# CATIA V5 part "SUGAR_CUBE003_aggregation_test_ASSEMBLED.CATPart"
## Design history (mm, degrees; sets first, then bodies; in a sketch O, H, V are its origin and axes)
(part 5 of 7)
Body41 "sugar_cube003Be004"
  Line260: type PtDir, RefPoint Point20, Direction edge [XY plane of AxisSystem1 | ZX plane of AxisSystem1], Start 0, End 3657.6 {= Body41.X1}
  Line261: type PtDir, RefPoint Point20, Direction edge [XY plane of AxisSystem1 | ZX plane of AxisSystem1], Start 0, End 6096 {= Body41.X2}
  Line262: type PtDir, RefPoint Point20, Direction edge [YZ plane of AxisSystem1 | XY plane of AxisSystem1], Start 0, End 5791.2 {= Body41.Y1}
  Line263: type PtDir, RefPoint Point20, Direction edge [YZ plane of AxisSystem1 | XY plane of AxisSystem1], Start 0, End 3962.4 {= Body41.Y2}
  Line264: type PtDir, RefPoint Point20, Direction edge [ZX plane of AxisSystem1 | YZ plane of AxisSystem1], Start 0, End 3352.8 {= Body41.Z1}
  Line265: type PtDir, RefPoint Point20, Direction edge [ZX plane of AxisSystem1 | YZ plane of AxisSystem1], Start 0, End 3962.4 {= Body41.Z2}
  Plane518: type Normal, Curve Line260, RefPoint vertex of Line260
  Plane519: type Normal, Curve Line261, RefPoint vertex of Line261
  Plane520: type Normal, Curve Line262, RefPoint vertex of Line262
  Plane521: type Normal, Curve Line263, RefPoint vertex of Line263
  Plane522: type Normal, Curve Line264, RefPoint vertex of Line264
  Plane523: type Normal, Curve Line265, RefPoint vertex of Line265
  Plane524: type 3Points, Element1 Point20, Element2 vertex of Line262, Element3 vertex of Line260
  Intersect781: ToIntersect1 Plane520, ToIntersect2 Plane519
  Intersect782: ToIntersect1 Plane518, ToIntersect2 Plane520
  Intersect783: ToIntersect1 Plane518, ToIntersect2 Plane521
  Intersect784: ToIntersect1 Plane521, ToIntersect2 Plane519
  MultiSel40
  LineCorner40: Elements ({intersect ToIntersect1 Plane524, ToIntersect2 Intersect783}; {intersect ToIntersect1 Plane524, ToIntersect2 Intersect784}; {intersect ToIntersect1 Plane524, ToIntersect2 Intersect781}; {intersect ToIntersect1 Plane524, ToIntersect2 Intersect782})
  Pad158: profile LineCorner40, up to Plane522, opposite side up to Plane523, deactivated
  Plane525: type Offset, RefPlane Plane521, Offset 609.6 {= thickness}
  Plane526: type Offset, RefPlane Plane520, Offset 609.6 {= thickness}, reversed
  Plane527: type Offset, RefPlane Plane518, Offset 609.6 {= thickness}, reversed
  Plane528: type Offset, RefPlane Plane519, Offset 609.6 {= thickness}
  Plane529: type Offset, RefPlane Plane523, Offset 609.6 {= thickness}
  Plane530: type Offset, RefPlane Plane522, Offset 609.6 {= thickness}, reversed
  Intersect785: ToIntersect1 Plane525, ToIntersect2 Plane518
  Intersect786: ToIntersect1 Plane526, ToIntersect2 Plane518
  Intersect787: ToIntersect1 Plane529, ToIntersect2 Plane518
  Intersect788: ToIntersect1 Plane530, ToIntersect2 Plane518
  Trim469: Trimmed (Intersect785; Intersect788)
  Trim470: Trimmed (Trim469; Intersect786)
  Trim471: Trimmed (Trim470; Intersect787)
  Pocket162: profile Trim471, up to Plane528, deactivated
  Pad159: profile LineCorner40, up to Plane522, opposite side up to Plane523, deactivated
  Intersect789: ToIntersect1 Plane526, ToIntersect2 Plane519
  Intersect790: ToIntersect1 Plane519, ToIntersect2 Plane525
  Intersect791: ToIntersect1 Plane529, ToIntersect2 Plane519
  Intersect792: ToIntersect1 Plane530, ToIntersect2 Plane519
  Trim472: Trimmed (Intersect792; Intersect789)
  Trim473: Trimmed (Trim472; Intersect791)
  Trim474: Trimmed (Trim473; Intersect790)
  Pocket163: profile Trim474, up to Plane527, deactivated
  Intersect793: ToIntersect1 Plane528, ToIntersect2 Plane521
  Intersect794: ToIntersect1 Plane529, ToIntersect2 Plane521
  Intersect795: ToIntersect1 Plane521, ToIntersect2 Plane527
  Intersect796: ToIntersect1 Plane530, ToIntersect2 Plane521
  Trim475: Trimmed (Intersect793; Intersect796)
  Trim476: Trimmed (Trim475; Intersect795)
  Trim477: Trimmed (Trim476; Intersect794)
  Pad160: profile LineCorner40, up to Plane522, opposite side up to Plane523, deactivated
  Pocket164: profile Trim477, up to Plane526, deactivated
  Intersect797: ToIntersect1 Plane527, ToIntersect2 Plane520
  Intersect798: ToIntersect1 Plane529, ToIntersect2 Plane520
  Intersect799: ToIntersect1 Plane528, ToIntersect2 Plane520
  Intersect800: ToIntersect1 Plane530, ToIntersect2 Plane520
  Trim478: Trimmed (Intersect797; Intersect800)
  Trim479: Trimmed (Trim478; Intersect799)
  Trim480: Trimmed (Trim479; Intersect798)
  Pad161: profile LineCorner40, up to Plane522, opposite side up to Plane523
  Pocket165: profile Trim480, up to Plane525
Body42 "sugar_cube003Ba005"
  Line266: type PtDir, RefPoint Point37, Direction edge [XY plane of AxisSystem1 | ZX plane of AxisSystem1], Start 0, End 4876.8 {= Body42.X1}
  Line267: type PtDir, RefPoint Point37, Direction edge [XY plane of AxisSystem1 | ZX plane of AxisSystem1], Start 0, End 4267.2 {= Body42.X2}
  Line268: type PtDir, RefPoint Point37, Direction edge [YZ plane of AxisSystem1 | XY plane of AxisSystem1], Start 0, End 4572 {= Body42.Y1}
  Line269: type PtDir, RefPoint Point37, Direction edge [YZ plane of AxisSystem1 | XY plane of AxisSystem1], Start 0, End 3352.8 {= Body42.Y2}
  Line270: type PtDir, RefPoint Point37, Direction edge [ZX plane of AxisSystem1 | YZ plane of AxisSystem1], Start 0, End 5486.4 {= Body42.Z1}
  Line271: type PtDir, RefPoint Point37, Direction edge [ZX plane of AxisSystem1 | YZ plane of AxisSystem1], Start 0, End 3048 {= Body42.Z2}
  Plane531: type Normal, Curve Line266, RefPoint vertex of Line266
  Plane532: type Normal, Curve Line267, RefPoint vertex of Line267
  Plane533: type Normal, Curve Line268, RefPoint vertex of Line268
  Plane534: type Normal, Curve Line269, RefPoint vertex of Line269
  Plane535: type Normal, Curve Line270, RefPoint vertex of Line270
  Plane536: type Normal, Curve Line271, RefPoint vertex of Line271
  Plane537: type 3Points, Element1 Point37, Element2 vertex of Line268, Element3 vertex of Line266
  Intersect801: ToIntersect1 Plane533, ToIntersect2 Plane532
  Intersect802: ToIntersect1 Plane531, ToIntersect2 Plane533
  Intersect803: ToIntersect1 Plane531, ToIntersect2 Plane534
  Intersect804: ToIntersect1 Plane534, ToIntersect2 Plane532
  MultiSel41
  LineCorner41: Elements ({intersect ToIntersect1 Plane537, ToIntersect2 Intersect803}; {intersect ToIntersect1 Plane537, ToIntersect2 Intersect804}; {intersect ToIntersect1 Plane537, ToIntersect2 Intersect801}; {intersect ToIntersect1 Plane537, ToIntersect2 Intersect802})
  Pad162: profile LineCorner41, up to Plane535, opposite side up to Plane536
  Plane538: type Offset, RefPlane Plane534, Offset 609.6 {= thickness}
  Plane539: type Offset, RefPlane Plane533, Offset 609.6 {= thickness}, reversed
  Plane540: type Offset, RefPlane Plane531, Offset 609.6 {= thickness}, reversed
  Plane541: type Offset, RefPlane Plane532, Offset 609.6 {= thickness}
  Plane542: type Offset, RefPlane Plane536, Offset 609.6 {= thickness}
  Plane543: type Offset, RefPlane Plane535, Offset 609.6 {= thickness}, reversed
  Intersect805: ToIntersect1 Plane538, ToIntersect2 Plane531
  Intersect806: ToIntersect1 Plane539, ToIntersect2 Plane531
  Intersect807: ToIntersect1 Plane542, ToIntersect2 Plane531
  Intersect808: ToIntersect1 Plane543, ToIntersect2 Plane531
  Trim481: Trimmed (Intersect805; Intersect808)
  Trim482: Trimmed (Trim481; Intersect806)
  Trim483: Trimmed (Trim482; Intersect807)
  Pocket166: profile Trim483, up to Plane541, deactivated
  Pad163: profile LineCorner41, up to Plane535, opposite side up to Plane536, deactivated
  Intersect809: ToIntersect1 Plane539, ToIntersect2 Plane532
  Intersect810: ToIntersect1 Plane532, ToIntersect2 Plane538
  Intersect811: ToIntersect1 Plane542, ToIntersect2 Plane532
  Intersect812: ToIntersect1 Plane543, ToIntersect2 Plane532
  Trim484: Trimmed (Intersect812; Intersect809)
  Trim485: Trimmed (Trim484; Intersect811)
  Trim486: Trimmed (Trim485; Intersect810)
  Pocket167: profile Trim486, up to Plane540, deactivated
  Intersect813: ToIntersect1 Plane541, ToIntersect2 Plane534
  Intersect814: ToIntersect1 Plane542, ToIntersect2 Plane534
  Intersect815: ToIntersect1 Plane534, ToIntersect2 Plane540
  Intersect816: ToIntersect1 Plane543, ToIntersect2 Plane534
  Trim487: Trimmed (Intersect813; Intersect816)
  Trim488: Trimmed (Trim487; Intersect815)
  Trim489: Trimmed (Trim488; Intersect814)
  Pad164: profile LineCorner41, up to Plane535, opposite side up to Plane536, deactivated
  Pocket168: profile Trim489, up to Plane539, deactivated
  Intersect817: ToIntersect1 Plane540, ToIntersect2 Plane533
  Intersect818: ToIntersect1 Plane542, ToIntersect2 Plane533
  Intersect819: ToIntersect1 Plane541, ToIntersect2 Plane533
  Intersect820: ToIntersect1 Plane543, ToIntersect2 Plane533
  Trim490: Trimmed (Intersect817; Intersect820)
  Trim491: Trimmed (Trim490; Intersect819)
  Trim492: Trimmed (Trim491; Intersect818)
  Pad165: profile LineCorner41, up to Plane535, opposite side up to Plane536, deactivated
  Pocket169: profile Trim492, up to Plane538, deactivated
Body43 "sugar_cube003Bb005"
  Line272: type PtDir, RefPoint Point33, Direction edge [XY plane of AxisSystem1 | ZX plane of AxisSystem1], Start 0, End 3048 {= Body43.X1}
  Line273: type PtDir, RefPoint Point33, Direction edge [XY plane of AxisSystem1 | ZX plane of AxisSystem1], Start 0, End 5486.4 {= Body43.X2}
  Line274: type PtDir, RefPoint Point33, Direction edge [YZ plane of AxisSystem1 | XY plane of AxisSystem1], Start 0, End 6096 {= Body43.Y1}
  Line275: type PtDir, RefPoint Point33, Direction edge [YZ plane of AxisSystem1 | XY plane of AxisSystem1], Start 0, End 3657.6 {= Body43.Y2}
  Line276: type PtDir, RefPoint Point33, Direction edge [ZX plane of AxisSystem1 | YZ plane of AxisSystem1], Start 0, End 4876.8 {= Body43.Z1}
  Line277: type PtDir, RefPoint Point33, Direction edge [ZX plane of AxisSystem1 | YZ plane of AxisSystem1], Start 0, End 5486.4 {= Body43.Z2}
  Plane544: type Normal, Curve Line272, RefPoint vertex of Line272
  Plane545: type Normal, Curve Line273, RefPoint vertex of Line273
  Plane546: type Normal, Curve Line274, RefPoint vertex of Line274
  Plane547: type Normal, Curve Line275, RefPoint vertex of Line275
  Plane548: type Normal, Curve Line276, RefPoint vertex of Line276
  Plane549: type Normal, Curve Line277, RefPoint vertex of Line277
  Plane550: type 3Points, Element1 Point33, Element2 vertex of Line274, Element3 vertex of Line272
  Intersect821: ToIntersect1 Plane546, ToIntersect2 Plane545
  Intersect822: ToIntersect1 Plane544, ToIntersect2 Plane546
  Intersect823: ToIntersect1 Plane544, ToIntersect2 Plane547
  Intersect824: ToIntersect1 Plane547, ToIntersect2 Plane545
  MultiSel42
  LineCorner42: Elements ({intersect ToIntersect1 Plane550, ToIntersect2 Intersect823}; {intersect ToIntersect1 Plane550, ToIntersect2 Intersect824}; {intersect ToIntersect1 Plane550, ToIntersect2 Intersect821}; {intersect ToIntersect1 Plane550, ToIntersect2 Intersect822})
  Pad166: profile LineCorner42, up to Plane548, opposite side up to Plane549
  Plane551: type Offset, RefPlane Plane547, Offset 609.6 {= thickness}
  Plane552: type Offset, RefPlane Plane546, Offset 609.6 {= thickness}, reversed
  Plane553: type Offset, RefPlane Plane544, Offset 609.6 {= thickness}, reversed
  Plane554: type Offset, RefPlane Plane545, Offset 609.6 {= thickness}
  Plane555: type Offset, RefPlane Plane549, Offset 609.6 {= thickness}
  Plane556: type Offset, RefPlane Plane548, Offset 609.6 {= thickness}, reversed
  Intersect825: ToIntersect1 Plane551, ToIntersect2 Plane544
  Intersect826: ToIntersect1 Plane552, ToIntersect2 Plane544
  Intersect827: ToIntersect1 Plane555, ToIntersect2 Plane544
  Intersect828: ToIntersect1 Plane556, ToIntersect2 Plane544
  Trim493: Trimmed (Intersect825; Intersect828)
  Trim494: Trimmed (Trim493; Intersect826)
  Trim495: Trimmed (Trim494; Intersect827)
  Pocket170: profile Trim495, up to Plane554, deactivated
  Pad167: profile LineCorner42, up to Plane548, opposite side up to Plane549
  Intersect829: ToIntersect1 Plane552, ToIntersect2 Plane545
  Intersect830: ToIntersect1 Plane545, ToIntersect2 Plane551
  Intersect831: ToIntersect1 Plane555, ToIntersect2 Plane545
  Intersect832: ToIntersect1 Plane556, ToIntersect2 Plane545
  Trim496: Trimmed (Intersect832; Intersect829)
  Trim497: Trimmed (Trim496; Intersect831)
  Trim498: Trimmed (Trim497; Intersect830)
  Pocket171: profile Trim498, up to Plane553
  Intersect833: ToIntersect1 Plane554, ToIntersect2 Plane547
  Intersect834: ToIntersect1 Plane555, ToIntersect2 Plane547
  Intersect835: ToIntersect1 Plane547, ToIntersect2 Plane553
  Intersect836: ToIntersect1 Plane556, ToIntersect2 Plane547
  Trim499: Trimmed (Intersect833; Intersect836)
  Trim500: Trimmed (Trim499; Intersect835)
  Trim501: Trimmed (Trim500; Intersect834)
  Pad168: profile LineCorner42, up to Plane548, opposite side up to Plane549, deactivated
  Pocket172: profile Trim501, up to Plane552, deactivated
  Intersect837: ToIntersect1 Plane553, ToIntersect2 Plane546
  Intersect838: ToIntersect1 Plane555, ToIntersect2 Plane546
  Intersect839: ToIntersect1 Plane554, ToIntersect2 Plane546
  Intersect840: ToIntersect1 Plane556, ToIntersect2 Plane546
  Trim502: Trimmed (Intersect837; Intersect840)
  Trim503: Trimmed (Trim502; Intersect839)
  Trim504: Trimmed (Trim503; Intersect838)
  Pad169: profile LineCorner42, up to Plane548, opposite side up to Plane549, deactivated
  Pocket173: profile Trim504, up to Plane551, deactivated
Body44 "sugar_cube003Bc005"
  Line278: type PtDir, RefPoint Point29, Direction edge [XY plane of AxisSystem1 | ZX plane of AxisSystem1], Start 0, End 4572 {= Body44.X1}
  Line279: type PtDir, RefPoint Point29, Direction edge [XY plane of AxisSystem1 | ZX plane of AxisSystem1], Start 0, End 4267.2 {= Body44.X2}
  Line280: type PtDir, RefPoint Point29, Direction edge [YZ plane of AxisSystem1 | XY plane of AxisSystem1], Start 0, End 3048 {= Body44.Y1}
  Line281: type PtDir, RefPoint Point29, Direction edge [YZ plane of AxisSystem1 | XY plane of AxisSystem1], Start 0, End 4876.8 {= Body44.Y2}
  Line282: type PtDir, RefPoint Point29, Direction edge [ZX plane of AxisSystem1 | YZ plane of AxisSystem1], Start 0, End 5486.4 {= Body44.Z1}
  Line283: type PtDir, RefPoint Point29, Direction edge [ZX plane of AxisSystem1 | YZ plane of AxisSystem1], Start 0, End 5486.4 {= Body44.Z2}
  Plane557: type Normal, Curve Line278, RefPoint vertex of Line278
  Plane558: type Normal, Curve Line279, RefPoint vertex of Line279
  Plane559: type Normal, Curve Line280, RefPoint vertex of Line280
  Plane560: type Normal, Curve Line281, RefPoint vertex of Line281
  Plane561: type Normal, Curve Line282, RefPoint vertex of Line282
  Plane562: type Normal, Curve Line283, RefPoint vertex of Line283
  Plane563: type 3Points, Element1 Point29, Element2 vertex of Line280, Element3 vertex of Line278
  Intersect841: ToIntersect1 Plane559, ToIntersect2 Plane558
  Intersect842: ToIntersect1 Plane557, ToIntersect2 Plane559
  Intersect843: ToIntersect1 Plane557, ToIntersect2 Plane560
  Intersect844: ToIntersect1 Plane560, ToIntersect2 Plane558
  MultiSel43
  LineCorner43: Elements ({intersect ToIntersect1 Plane563, ToIntersect2 Intersect843}; {intersect ToIntersect1 Plane563, ToIntersect2 Intersect844}; {intersect ToIntersect1 Plane563, ToIntersect2 Intersect841}; {intersect ToIntersect1 Plane563, ToIntersect2 Intersect842})
  Pad170: profile LineCorner43, up to Plane561, opposite side up to Plane562
  Plane564: type Offset, RefPlane Plane560, Offset 609.6 {= thickness}
  Plane565: type Offset, RefPlane Plane559, Offset 609.6 {= thickness}, reversed
  Plane566: type Offset, RefPlane Plane557, Offset 609.6 {= thickness}, reversed
  Plane567: type Offset, RefPlane Plane558, Offset 609.6 {= thickness}
  Plane568: type Offset, RefPlane Plane562, Offset 609.6 {= thickness}
  Plane569: type Offset, RefPlane Plane561, Offset 609.6 {= thickness}, reversed
  Intersect845: ToIntersect1 Plane564, ToIntersect2 Plane557
  Intersect846: ToIntersect1 Plane565, ToIntersect2 Plane557
  Intersect847: ToIntersect1 Plane568, ToIntersect2 Plane557
  Intersect848: ToIntersect1 Plane569, ToIntersect2 Plane557
  Trim505: Trimmed (Intersect845; Intersect848)
  Trim506: Trimmed (Trim505; Intersect846)
  Trim507: Trimmed (Trim506; Intersect847)
  Pocket174: profile Trim507, up to Plane567, deactivated
  Pad171: profile LineCorner43, up to Plane561, opposite side up to Plane562
  Intersect849: ToIntersect1 Plane565, ToIntersect2 Plane558
  Intersect850: ToIntersect1 Plane558, ToIntersect2 Plane564
  Intersect851: ToIntersect1 Plane568, ToIntersect2 Plane558
  Intersect852: ToIntersect1 Plane569, ToIntersect2 Plane558
  Trim508: Trimmed (Intersect852; Intersect849)
  Trim509: Trimmed (Trim508; Intersect851)
  Trim510: Trimmed (Trim509; Intersect850)
  Pocket175: profile Trim510, up to Plane566
  Intersect853: ToIntersect1 Plane567, ToIntersect2 Plane560
  Intersect854: ToIntersect1 Plane568, ToIntersect2 Plane560
  Intersect855: ToIntersect1 Plane560, ToIntersect2 Plane566
  Intersect856: ToIntersect1 Plane569, ToIntersect2 Plane560
  Trim511: Trimmed (Intersect853; Intersect856)
  Trim512: Trimmed (Trim511; Intersect855)
  Trim513: Trimmed (Trim512; Intersect854)
  Pad172: profile LineCorner43, up to Plane561, opposite side up to Plane562, deactivated
  Pocket176: profile Trim513, up to Plane565, deactivated
  Intersect857: ToIntersect1 Plane566, ToIntersect2 Plane559
  Intersect858: ToIntersect1 Plane568, ToIntersect2 Plane559
  Intersect859: ToIntersect1 Plane567, ToIntersect2 Plane559
  Intersect860: ToIntersect1 Plane569, ToIntersect2 Plane559
  Trim514: Trimmed (Intersect857; Intersect860)
  Trim515: Trimmed (Trim514; Intersect859)
  Trim516: Trimmed (Trim515; Intersect858)
  Pad173: profile LineCorner43, up to Plane561, opposite side up to Plane562, deactivated
  Pocket177: profile Trim516, up to Plane564, deactivated
Body45 "sugar_cube003Bd005"
  Line284: type PtDir, RefPoint Point25, Direction edge [XY plane of AxisSystem1 | ZX plane of AxisSystem1], Start 0, End 3352.8 {= Body45.X1}
  Line285: type PtDir, RefPoint Point25, Direction edge [XY plane of AxisSystem1 | ZX plane of AxisSystem1], Start 0, End 4267.2 {= Body45.X2}
  Line286: type PtDir, RefPoint Point25, Direction edge [YZ plane of AxisSystem1 | XY plane of AxisSystem1], Start 0, End 4572 {= Body45.Y1}
  Line287: type PtDir, RefPoint Point25, Direction edge [YZ plane of AxisSystem1 | XY plane of AxisSystem1], Start 0, End 3962.4 {= Body45.Y2}
  Line288: type PtDir, RefPoint Point25, Direction edge [ZX plane of AxisSystem1 | YZ plane of AxisSystem1], Start 0, End 5181.6 {= Body45.Z1}
  Line289: type PtDir, RefPoint Point25, Direction edge [ZX plane of AxisSystem1 | YZ plane of AxisSystem1], Start 0, End 5181.6 {= Body45.Z2}
  Plane570: type Normal, Curve Line284, RefPoint vertex of Line284
  Plane571: type Normal, Curve Line285, RefPoint vertex of Line285
  Plane572: type Normal, Curve Line286, RefPoint vertex of Line286
  Plane573: type Normal, Curve Line287, RefPoint vertex of Line287
  Plane574: type Normal, Curve Line288, RefPoint vertex of Line288
  Plane575: type Normal, Curve Line289, RefPoint vertex of Line289
  Plane576: type 3Points, Element1 Point25, Element2 vertex of Line286, Element3 vertex of Line284
  Intersect861: ToIntersect1 Plane572, ToIntersect2 Plane571
  Intersect862: ToIntersect1 Plane570, ToIntersect2 Plane572
  Intersect863: ToIntersect1 Plane570, ToIntersect2 Plane573
  Intersect864: ToIntersect1 Plane573, ToIntersect2 Plane571
  MultiSel44
  LineCorner44: Elements ({intersect ToIntersect1 Plane576, ToIntersect2 Intersect863}; {intersect ToIntersect1 Plane576, ToIntersect2 Intersect864}; {intersect ToIntersect1 Plane576, ToIntersect2 Intersect861}; {intersect ToIntersect1 Plane576, ToIntersect2 Intersect862})
  Pad174: profile LineCorner44, up to Plane574, opposite side up to Plane575, deactivated
  Plane577: type Offset, RefPlane Plane573, Offset 609.6 {= thickness}
  Plane578: type Offset, RefPlane Plane572, Offset 609.6 {= thickness}, reversed
  Plane579: type Offset, RefPlane Plane570, Offset 609.6 {= thickness}, reversed
  Plane580: type Offset, RefPlane Plane571, Offset 609.6 {= thickness}
  Plane581: type Offset, RefPlane Plane575, Offset 609.6 {= thickness}
  Plane582: type Offset, RefPlane Plane574, Offset 609.6 {= thickness}, reversed
  Intersect865: ToIntersect1 Plane577, ToIntersect2 Plane570
  Intersect866: ToIntersect1 Plane578, ToIntersect2 Plane570
  Intersect867: ToIntersect1 Plane581, ToIntersect2 Plane570
  Intersect868: ToIntersect1 Plane582, ToIntersect2 Plane570
  Trim517: Trimmed (Intersect865; Intersect868)
  Trim518: Trimmed (Trim517; Intersect866)
  Trim519: Trimmed (Trim518; Intersect867)
  Pocket178: profile Trim519, up to Plane580, deactivated
  Pad175: profile LineCorner44, up to Plane574, opposite side up to Plane575, deactivated
  Intersect869: ToIntersect1 Plane578, ToIntersect2 Plane571
  Intersect870: ToIntersect1 Plane571, ToIntersect2 Plane577
  Intersect871: ToIntersect1 Plane581, ToIntersect2 Plane571
  Intersect872: ToIntersect1 Plane582, ToIntersect2 Plane571
  Trim520: Trimmed (Intersect872; Intersect869)
  Trim521: Trimmed (Trim520; Intersect871)
  Trim522: Trimmed (Trim521; Intersect870)
  Pocket179: profile Trim522, up to Plane579, deactivated
  Intersect873: ToIntersect1 Plane580, ToIntersect2 Plane573
  Intersect874: ToIntersect1 Plane581, ToIntersect2 Plane573
  Intersect875: ToIntersect1 Plane573, ToIntersect2 Plane579
  Intersect876: ToIntersect1 Plane582, ToIntersect2 Plane573
  Trim523: Trimmed (Intersect873; Intersect876)
  Trim524: Trimmed (Trim523; Intersect875)
  Trim525: Trimmed (Trim524; Intersect874)
  Pad176: profile LineCorner44, up to Plane574, opposite side up to Plane575, deactivated
  Pocket180: profile Trim525, up to Plane578, deactivated
  Intersect877: ToIntersect1 Plane579, ToIntersect2 Plane572
  Intersect878: ToIntersect1 Plane581, ToIntersect2 Plane572
  Intersect879: ToIntersect1 Plane580, ToIntersect2 Plane572
  Intersect880: ToIntersect1 Plane582, ToIntersect2 Plane572
  Trim526: Trimmed (Intersect877; Intersect880)
  Trim527: Trimmed (Trim526; Intersect879)
  Trim528: Trimmed (Trim527; Intersect878)
  Pad177: profile LineCorner44, up to Plane574, opposite side up to Plane575, deactivated
  Pocket181: profile Trim528, up to Plane577, deactivated
Body46 "sugar_cube003Be005"
  Line290: type PtDir, RefPoint Point21, Direction edge [XY plane of AxisSystem1 | ZX plane of AxisSystem1], Start 0, End 4876.8 {= Body46.X1}
  Line291: type PtDir, RefPoint Point21, Direction edge [XY plane of AxisSystem1 | ZX plane of AxisSystem1], Start 0, End 4267.2 {= Body46.X2}
  Line292: type PtDir, RefPoint Point21, Direction edge [YZ plane of AxisSystem1 | XY plane of AxisSystem1], Start 0, End 5791.2 {= Body46.Y1}
  Line293: type PtDir, RefPoint Point21, Direction edge [YZ plane of AxisSystem1 | XY plane of AxisSystem1], Start 0, End 4267.2 {= Body46.Y2}
  Line294: type PtDir, RefPoint Point21, Direction edge [ZX plane of AxisSystem1 | YZ plane of AxisSystem1], Start 0, End 5181.6 {= Body46.Z1}
  Line295: type PtDir, RefPoint Point21, Direction edge [ZX plane of AxisSystem1 | YZ plane of AxisSystem1], Start 0, End 5791.2 {= Body46.Z2}
  Plane583: type Normal, Curve Line290, RefPoint vertex of Line290
  Plane584: type Normal, Curve Line291, RefPoint vertex of Line291
  Plane585: type Normal, Curve Line292, RefPoint vertex of Line292
  Plane586: type Normal, Curve Line293, RefPoint vertex of Line293
  Plane587: type Normal, Curve Line294, RefPoint vertex of Line294
  Plane588: type Normal, Curve Line295, RefPoint vertex of Line295
  Plane589: type 3Points, Element1 Point21, Element2 vertex of Line292, Element3 vertex of Line290
  Intersect881: ToIntersect1 Plane585, ToIntersect2 Plane584
  Intersect882: ToIntersect1 Plane583, ToIntersect2 Plane585
  Intersect883: ToIntersect1 Plane583, ToIntersect2 Plane586
  Intersect884: ToIntersect1 Plane586, ToIntersect2 Plane584
  MultiSel45
  LineCorner45: Elements ({intersect ToIntersect1 Plane589, ToIntersect2 Intersect883}; {intersect ToIntersect1 Plane589, ToIntersect2 Intersect884}; {intersect ToIntersect1 Plane589, ToIntersect2 Intersect881}; {intersect ToIntersect1 Plane589, ToIntersect2 Intersect882})
  Pad178: profile LineCorner45, up to Plane587, opposite side up to Plane588
  Plane590: type Offset, RefPlane Plane586, Offset 609.6 {= thickness}
  Plane591: type Offset, RefPlane Plane585, Offset 609.6 {= thickness}, reversed
  Plane592: type Offset, RefPlane Plane583, Offset 609.6 {= thickness}, reversed
  Plane593: type Offset, RefPlane Plane584, Offset 609.6 {= thickness}
  Plane594: type Offset, RefPlane Plane588, Offset 609.6 {= thickness}
  Plane595: type Offset, RefPlane Plane587, Offset 609.6 {= thickness}, reversed
  Intersect885: ToIntersect1 Plane590, ToIntersect2 Plane583
  Intersect886: ToIntersect1 Plane591, ToIntersect2 Plane583
  Intersect887: ToIntersect1 Plane594, ToIntersect2 Plane583
  Intersect888: ToIntersect1 Plane595, ToIntersect2 Plane583
  Trim529: Trimmed (Intersect885; Intersect888)
  Trim530: Trimmed (Trim529; Intersect886)
  Trim531: Trimmed (Trim530; Intersect887)
  Pocket182: profile Trim531, up to Plane593, deactivated
  Pad179: profile LineCorner45, up to Plane587, opposite side up to Plane588, deactivated
  Intersect889: ToIntersect1 Plane591, ToIntersect2 Plane584
  Intersect890: ToIntersect1 Plane584, ToIntersect2 Plane590
  Intersect891: ToIntersect1 Plane594, ToIntersect2 Plane584
  Intersect892: ToIntersect1 Plane595, ToIntersect2 Plane584
  Trim532: Trimmed (Intersect892; Intersect889)
  Trim533: Trimmed (Trim532; Intersect891)
  Trim534: Trimmed (Trim533; Intersect890)
  Pocket183: profile Trim534, up to Plane592, deactivated
  Intersect893: ToIntersect1 Plane593, ToIntersect2 Plane586
  Intersect894: ToIntersect1 Plane594, ToIntersect2 Plane586
  Intersect895: ToIntersect1 Plane586, ToIntersect2 Plane592
  Intersect896: ToIntersect1 Plane595, ToIntersect2 Plane586
  Trim535: Trimmed (Intersect893; Intersect896)
  Trim536: Trimmed (Trim535; Intersect895)
  Trim537: Trimmed (Trim536; Intersect894)
  Pad180: profile LineCorner45, up to Plane587, opposite side up to Plane588, deactivated
  Pocket184: profile Trim537, up to Plane591, deactivated
  Intersect897: ToIntersect1 Plane592, ToIntersect2 Plane585
  Intersect898: ToIntersect1 Plane594, ToIntersect2 Plane585
  Intersect899: ToIntersect1 Plane593, ToIntersect2 Plane585
  Intersect900: ToIntersect1 Plane595, ToIntersect2 Plane585
  Trim538: Trimmed (Intersect897; Intersect900)
  Trim539: Trimmed (Trim538; Intersect899)
  Trim540: Trimmed (Trim539; Intersect898)
  Pad181: profile LineCorner45, up to Plane587, opposite side up to Plane588
  Pocket185: profile Trim540, up to Plane590
Body47 "sugar_cube003Ba006"
  Line296: type PtDir, RefPoint vertex of Line9, Direction edge [XY plane of AxisSystem1 | ZX plane of AxisSystem1], Start 0, End 4876.8 {= Body47.X1}
  Line297: type PtDir, RefPoint vertex of Line9, Direction edge [XY plane of AxisSystem1 | ZX plane of AxisSystem1], Start 0, End 4876.8 {= Body47.X2}
  Line298: type PtDir, RefPoint vertex of Line9, Direction edge [YZ plane of AxisSystem1 | XY plane of AxisSystem1], Start 0, End 3352.8 {= Body47.Y1}
  Line299: type PtDir, RefPoint vertex of Line9, Direction edge [YZ plane of AxisSystem1 | XY plane of AxisSystem1], Start 0, End 3657.6 {= Body47.Y2}
  Line300: type PtDir, RefPoint vertex of Line9, Direction edge [ZX plane of AxisSystem1 | YZ plane of AxisSystem1], Start 0, End 4572 {= Body47.Z1}
  Line301: type PtDir, RefPoint vertex of Line9, Direction edge [ZX plane of AxisSystem1 | YZ plane of AxisSystem1], Start 0, End 6096 {= Body47.Z2}
  Plane596: type Normal, Curve Line296, RefPoint vertex of Line296
  Plane597: type Normal, Curve Line297, RefPoint vertex of Line297
  Plane598: type Normal, Curve Line298, RefPoint vertex of Line298
  Plane599: type Normal, Curve Line299, RefPoint vertex of Line299
  Plane600: type Normal, Curve Line300, RefPoint vertex of Line300
  Plane601: type Normal, Curve Line301, RefPoint vertex of Line301
  Plane602: type 3Points, Element1 vertex of Line9, Element2 vertex of Line298, Element3 vertex of Line296
  Intersect901: ToIntersect1 Plane598, ToIntersect2 Plane597
  Intersect902: ToIntersect1 Plane596, ToIntersect2 Plane598
  Intersect903: ToIntersect1 Plane596, ToIntersect2 Plane599
  Intersect904: ToIntersect1 Plane599, ToIntersect2 Plane597
  MultiSel46
  LineCorner46: Elements ({intersect ToIntersect1 Plane602, ToIntersect2 Intersect903}; {intersect ToIntersect1 Plane602, ToIntersect2 Intersect904}; {intersect ToIntersect1 Plane602, ToIntersect2 Intersect901}; {intersect ToIntersect1 Plane602, ToIntersect2 Intersect902})
  Pad182: profile LineCorner46, up to Plane600, opposite side up to Plane601
  Plane603: type Offset, RefPlane Plane599, Offset 609.6 {= thickness}
  Plane604: type Offset, RefPlane Plane598, Offset 609.6 {= thickness}, reversed
  Plane605: type Offset, RefPlane Plane596, Offset 609.6 {= thickness}, reversed
  Plane606: type Offset, RefPlane Plane597, Offset 609.6 {= thickness}
  Plane607: type Offset, RefPlane Plane601, Offset 609.6 {= thickness}
  Plane608: type Offset, RefPlane Plane600, Offset 609.6 {= thickness}, reversed
  Intersect905: ToIntersect1 Plane603, ToIntersect2 Plane596
  Intersect906: ToIntersect1 Plane604, ToIntersect2 Plane596
  Intersect907: ToIntersect1 Plane607, ToIntersect2 Plane596
  Intersect908: ToIntersect1 Plane608, ToIntersect2 Plane596
  Trim541: Trimmed (Intersect905; Intersect908)
  Trim542: Trimmed (Trim541; Intersect906)
  Trim543: Trimmed (Trim542; Intersect907)
  Pocket186: profile Trim543, up to Plane606, deactivated
  Pad183: profile LineCorner46, up to Plane600, opposite side up to Plane601, deactivated
  Intersect909: ToIntersect1 Plane604, ToIntersect2 Plane597
  Intersect910: ToIntersect1 Plane597, ToIntersect2 Plane603
  Intersect911: ToIntersect1 Plane607, ToIntersect2 Plane597
  Intersect912: ToIntersect1 Plane608, ToIntersect2 Plane597
  Trim544: Trimmed (Intersect912; Intersect909)
  Trim545: Trimmed (Trim544; Intersect911)
  Trim546: Trimmed (Trim545; Intersect910)
  Pocket187: profile Trim546, up to Plane605, deactivated
  Intersect913: ToIntersect1 Plane606, ToIntersect2 Plane599
  Intersect914: ToIntersect1 Plane607, ToIntersect2 Plane599
  Intersect915: ToIntersect1 Plane599, ToIntersect2 Plane605
  Intersect916: ToIntersect1 Plane608, ToIntersect2 Plane599
  Trim547: Trimmed (Intersect913; Intersect916)
  Trim548: Trimmed (Trim547; Intersect915)
  Trim549: Trimmed (Trim548; Intersect914)
  Pad184: profile LineCorner46, up to Plane600, opposite side up to Plane601, deactivated
  Pocket188: profile Trim549, up to Plane604, deactivated
  Intersect917: ToIntersect1 Plane605, ToIntersect2 Plane598
  Intersect918: ToIntersect1 Plane607, ToIntersect2 Plane598
  Intersect919: ToIntersect1 Plane606, ToIntersect2 Plane598
  Intersect920: ToIntersect1 Plane608, ToIntersect2 Plane598
  Trim550: Trimmed (Intersect917; Intersect920)
  Trim551: Trimmed (Trim550; Intersect919)
  Trim552: Trimmed (Trim551; Intersect918)
  Pad185: profile LineCorner46, up to Plane600, opposite side up to Plane601, deactivated
  Pocket189: profile Trim552, up to Plane603, deactivated
Body48 "sugar_cube003Bb006"
  Line302: type PtDir, RefPoint vertex of Line8, Direction edge [XY plane of AxisSystem1 | ZX plane of AxisSystem1], Start 0, End 5791.2 {= Body48.X1}
  Line303: type PtDir, RefPoint vertex of Line8, Direction edge [XY plane of AxisSystem1 | ZX plane of AxisSystem1], Start 0, End 3962.4 {= Body48.X2}
  Line304: type PtDir, RefPoint vertex of Line8, Direction edge [YZ plane of AxisSystem1 | XY plane of AxisSystem1], Start 0, End 4267.2 {= Body48.Y1}
  Line305: type PtDir, RefPoint vertex of Line8, Direction edge [YZ plane of AxisSystem1 | XY plane of AxisSystem1], Start 0, End 5181.6 {= Body48.Y2}
  Line306: type PtDir, RefPoint vertex of Line8, Direction edge [ZX plane of AxisSystem1 | YZ plane of AxisSystem1], Start 0, End 5181.6 {= Body48.Z1}
  Line307: type PtDir, RefPoint vertex of Line8, Direction edge [ZX plane of AxisSystem1 | YZ plane of AxisSystem1], Start 0, End 3962.4 {= Body48.Z2}
  Plane609: type Normal, Curve Line302, RefPoint vertex of Line302
  Plane610: type Normal, Curve Line303, RefPoint vertex of Line303
  Plane611: type Normal, Curve Line304, RefPoint vertex of Line304
  Plane612: type Normal, Curve Line305, RefPoint vertex of Line305
  Plane613: type Normal, Curve Line306, RefPoint vertex of Line306
  Plane614: type Normal, Curve Line307, RefPoint vertex of Line307
  Plane615: type 3Points, Element1 vertex of Line8, Element2 vertex of Line304, Element3 vertex of Line302
  Intersect921: ToIntersect1 Plane611, ToIntersect2 Plane610
  Intersect922: ToIntersect1 Plane609, ToIntersect2 Plane611
  Intersect923: ToIntersect1 Plane609, ToIntersect2 Plane612
  Intersect924: ToIntersect1 Plane612, ToIntersect2 Plane610
  MultiSel47
  LineCorner47: Elements ({intersect ToIntersect1 Plane615, ToIntersect2 Intersect923}; {intersect ToIntersect1 Plane615, ToIntersect2 Intersect924}; {intersect ToIntersect1 Plane615, ToIntersect2 Intersect921}; {intersect ToIntersect1 Plane615, ToIntersect2 Intersect922})
  Pad186: profile LineCorner47, up to Plane613, opposite side up to Plane614
  Plane616: type Offset, RefPlane Plane612, Offset 609.6 {= thickness}
  Plane617: type Offset, RefPlane Plane611, Offset 609.6 {= thickness}, reversed
  Plane618: type Offset, RefPlane Plane609, Offset 609.6 {= thickness}, reversed
  Plane619: type Offset, RefPlane Plane610, Offset 609.6 {= thickness}
  Plane620: type Offset, RefPlane Plane614, Offset 609.6 {= thickness}
  Plane621: type Offset, RefPlane Plane613, Offset 609.6 {= thickness}, reversed
  Intersect925: ToIntersect1 Plane616, ToIntersect2 Plane609
  Intersect926: ToIntersect1 Plane617, ToIntersect2 Plane609
  Intersect927: ToIntersect1 Plane620, ToIntersect2 Plane609
  Intersect928: ToIntersect1 Plane621, ToIntersect2 Plane609
  Trim553: Trimmed (Intersect925; Intersect928)
  Trim554: Trimmed (Trim553; Intersect926)
  Trim555: Trimmed (Trim554; Intersect927)
  Pocket190: profile Trim555, up to Plane619
  Pad187: profile LineCorner47, up to Plane613, opposite side up to Plane614, deactivated
  Intersect929: ToIntersect1 Plane617, ToIntersect2 Plane610
  Intersect930: ToIntersect1 Plane610, ToIntersect2 Plane616
  Intersect931: ToIntersect1 Plane620, ToIntersect2 Plane610
  Intersect932: ToIntersect1 Plane621, ToIntersect2 Plane610
  Trim556: Trimmed (Intersect932; Intersect929)
  Trim557: Trimmed (Trim556; Intersect931)
  Trim558: Trimmed (Trim557; Intersect930)
  Pocket191: profile Trim558, up to Plane618, deactivated
  Intersect933: ToIntersect1 Plane619, ToIntersect2 Plane612
  Intersect934: ToIntersect1 Plane620, ToIntersect2 Plane612
  Intersect935: ToIntersect1 Plane612, ToIntersect2 Plane618
  Intersect936: ToIntersect1 Plane621, ToIntersect2 Plane612
  Trim559: Trimmed (Intersect933; Intersect936)
  Trim560: Trimmed (Trim559; Intersect935)
  Trim561: Trimmed (Trim560; Intersect934)
  Pad188: profile LineCorner47, up to Plane613, opposite side up to Plane614, deactivated
  Pocket192: profile Trim561, up to Plane617, deactivated
  Intersect937: ToIntersect1 Plane618, ToIntersect2 Plane611
  Intersect938: ToIntersect1 Plane620, ToIntersect2 Plane611
  Intersect939: ToIntersect1 Plane619, ToIntersect2 Plane611
  Intersect940: ToIntersect1 Plane621, ToIntersect2 Plane611
  Trim562: Trimmed (Intersect937; Intersect940)
  Trim563: Trimmed (Trim562; Intersect939)
  Trim564: Trimmed (Trim563; Intersect938)
  Pad189: profile LineCorner47, up to Plane613, opposite side up to Plane614, deactivated
  Pocket193: profile Trim564, up to Plane616, deactivated
Body49 "sugar_cube003Bc006"
  Line308: type PtDir, RefPoint vertex of Line7, Direction edge [XY plane of AxisSystem1 | ZX plane of AxisSystem1], Start 0, End 5181.6 {= Body49.X1}
  Line309: type PtDir, RefPoint vertex of Line7, Direction edge [XY plane of AxisSystem1 | ZX plane of AxisSystem1], Start 0, End 3352.8 {= Body49.X2}
  Line310: type PtDir, RefPoint vertex of Line7, Direction edge [YZ plane of AxisSystem1 | XY plane of AxisSystem1], Start 0, End 5181.6 {= Body49.Y1}
  Line311: type PtDir, RefPoint vertex of Line7, Direction edge [YZ plane of AxisSystem1 | XY plane of AxisSystem1], Start 0, End 5791.2 {= Body49.Y2}
  Line312: type PtDir, RefPoint vertex of Line7, Direction edge [ZX plane of AxisSystem1 | YZ plane of AxisSystem1], Start 0, End 3352.8 {= Body49.Z1}
  Line313: type PtDir, RefPoint vertex of Line7, Direction edge [ZX plane of AxisSystem1 | YZ plane of AxisSystem1], Start 0, End 5486.4 {= Body49.Z2}
  Plane622: type Normal, Curve Line308, RefPoint vertex of Line308
  Plane623: type Normal, Curve Line309, RefPoint vertex of Line309
  Plane624: type Normal, Curve Line310, RefPoint vertex of Line310
  Plane625: type Normal, Curve Line311, RefPoint vertex of Line311
  Plane626: type Normal, Curve Line312, RefPoint vertex of Line312
  Plane627: type Normal, Curve Line313, RefPoint vertex of Line313
  Plane628: type 3Points, Element1 vertex of Line7, Element2 vertex of Line310, Element3 vertex of Line308
  Intersect941: ToIntersect1 Plane624, ToIntersect2 Plane623
  Intersect942: ToIntersect1 Plane622, ToIntersect2 Plane624
  Intersect943: ToIntersect1 Plane622, ToIntersect2 Plane625
  Intersect944: ToIntersect1 Plane625, ToIntersect2 Plane623
  MultiSel48
  LineCorner48: Elements ({intersect ToIntersect1 Plane628, ToIntersect2 Intersect943}; {intersect ToIntersect1 Plane628, ToIntersect2 Intersect944}; {intersect ToIntersect1 Plane628, ToIntersect2 Intersect941}; {intersect ToIntersect1 Plane628, ToIntersect2 Intersect942})
  Pad190: profile LineCorner48, up to Plane626, opposite side up to Plane627
  Plane629: type Offset, RefPlane Plane625, Offset 609.6 {= thickness}
  Plane630: type Offset, RefPlane Plane624, Offset 609.6 {= thickness}, reversed
  Plane631: type Offset, RefPlane Plane622, Offset 609.6 {= thickness}, reversed
  Plane632: type Offset, RefPlane Plane623, Offset 609.6 {= thickness}
  Plane633: type Offset, RefPlane Plane627, Offset 609.6 {= thickness}
  Plane634: type Offset, RefPlane Plane626, Offset 609.6 {= thickness}, reversed
  Intersect945: ToIntersect1 Plane629, ToIntersect2 Plane622
  Intersect946: ToIntersect1 Plane630, ToIntersect2 Plane622
  Intersect947: ToIntersect1 Plane633, ToIntersect2 Plane622
  Intersect948: ToIntersect1 Plane634, ToIntersect2 Plane622
  Trim565: Trimmed (Intersect945; Intersect948)
  Trim566: Trimmed (Trim565; Intersect946)
  Trim567: Trimmed (Trim566; Intersect947)
  Pocket194: profile Trim567, up to Plane632, deactivated
  Pad191: profile LineCorner48, up to Plane626, opposite side up to Plane627, deactivated
  Intersect949: ToIntersect1 Plane630, ToIntersect2 Plane623
  Intersect950: ToIntersect1 Plane623, ToIntersect2 Plane629
  Intersect951: ToIntersect1 Plane633, ToIntersect2 Plane623
  Intersect952: ToIntersect1 Plane634, ToIntersect2 Plane623
  Trim568: Trimmed (Intersect952; Intersect949)
  Trim569: Trimmed (Trim568; Intersect951)
  Trim570: Trimmed (Trim569; Intersect950)
  Pocket195: profile Trim570, up to Plane631, deactivated
  Intersect953: ToIntersect1 Plane632, ToIntersect2 Plane625
  Intersect954: ToIntersect1 Plane633, ToIntersect2 Plane625
  Intersect955: ToIntersect1 Plane625, ToIntersect2 Plane631
  Intersect956: ToIntersect1 Plane634, ToIntersect2 Plane625
  Trim571: Trimmed (Intersect953; Intersect956)
  Trim572: Trimmed (Trim571; Intersect955)
  Trim573: Trimmed (Trim572; Intersect954)
  Pad192: profile LineCorner48, up to Plane626, opposite side up to Plane627, deactivated
  Pocket196: profile Trim573, up to Plane630, deactivated
  Intersect957: ToIntersect1 Plane631, ToIntersect2 Plane624
  Intersect958: ToIntersect1 Plane633, ToIntersect2 Plane624
  Intersect959: ToIntersect1 Plane632, ToIntersect2 Plane624
  Intersect960: ToIntersect1 Plane634, ToIntersect2 Plane624
  Trim574: Trimmed (Intersect957; Intersect960)
  Trim575: Trimmed (Trim574; Intersect959)
  Trim576: Trimmed (Trim575; Intersect958)
  Pad193: profile LineCorner48, up to Plane626, opposite side up to Plane627, deactivated
  Pocket197: profile Trim576, up to Plane629, deactivated
Body50 "sugar_cube003Bd006"
  Line314: type PtDir, RefPoint vertex of Line6, Direction edge [XY plane of AxisSystem1 | ZX plane of AxisSystem1], Start 0, End 5181.6 {= Body50.X1}
  Line315: type PtDir, RefPoint vertex of Line6, Direction edge [XY plane of AxisSystem1 | ZX plane of AxisSystem1], Start 0, End 3657.6 {= Body50.X2}
  Line316: type PtDir, RefPoint vertex of Line6, Direction edge [YZ plane of AxisSystem1 | XY plane of AxisSystem1], Start 0, End 4572 {= Body50.Y1}
  Line317: type PtDir, RefPoint vertex of Line6, Direction edge [YZ plane of AxisSystem1 | XY plane of AxisSystem1], Start 0, End 4572 {= Body50.Y2}
  Line318: type PtDir, RefPoint vertex of Line6, Direction edge [ZX plane of AxisSystem1 | YZ plane of AxisSystem1], Start 0, End 3657.6 {= Body50.Z1}
  Line319: type PtDir, RefPoint vertex of Line6, Direction edge [ZX plane of AxisSystem1 | YZ plane of AxisSystem1], Start 0, End 4572 {= Body50.Z2}
  Plane635: type Normal, Curve Line314, RefPoint vertex of Line314
  Plane636: type Normal, Curve Line315, RefPoint vertex of Line315
  Plane637: type Normal, Curve Line316, RefPoint vertex of Line316
  Plane638: type Normal, Curve Line317, RefPoint vertex of Line317
  Plane639: type Normal, Curve Line318, RefPoint vertex of Line318
  Plane640: type Normal, Curve Line319, RefPoint vertex of Line319
  Plane641: type 3Points, Element1 vertex of Line6, Element2 vertex of Line316, Element3 vertex of Line314
  Intersect961: ToIntersect1 Plane637, ToIntersect2 Plane636
  Intersect962: ToIntersect1 Plane635, ToIntersect2 Plane637
  Intersect963: ToIntersect1 Plane635, ToIntersect2 Plane638
  Intersect964: ToIntersect1 Plane638, ToIntersect2 Plane636
  MultiSel49
  LineCorner49: Elements ({intersect ToIntersect1 Plane641, ToIntersect2 Intersect963}; {intersect ToIntersect1 Plane641, ToIntersect2 Intersect964}; {intersect ToIntersect1 Plane641, ToIntersect2 Intersect961}; {intersect ToIntersect1 Plane641, ToIntersect2 Intersect962})
  Pad194: profile LineCorner49, up to Plane639, opposite side up to Plane640
  Plane642: type Offset, RefPlane Plane638, Offset 609.6 {= thickness}
  Plane643: type Offset, RefPlane Plane637, Offset 609.6 {= thickness}, reversed
  Plane644: type Offset, RefPlane Plane635, Offset 609.6 {= thickness}, reversed
  Plane645: type Offset, RefPlane Plane636, Offset 609.6 {= thickness}
  Plane646: type Offset, RefPlane Plane640, Offset 609.6 {= thickness}
  Plane647: type Offset, RefPlane Plane639, Offset 609.6 {= thickness}, reversed
  Intersect965: ToIntersect1 Plane642, ToIntersect2 Plane635
  Intersect966: ToIntersect1 Plane643, ToIntersect2 Plane635
  Intersect967: ToIntersect1 Plane646, ToIntersect2 Plane635
  Intersect968: ToIntersect1 Plane647, ToIntersect2 Plane635
  Trim577: Trimmed (Intersect965; Intersect968)
  Trim578: Trimmed (Trim577; Intersect966)
  Trim579: Trimmed (Trim578; Intersect967)
  Pocket198: profile Trim579, up to Plane645, deactivated
  Pad195: profile LineCorner49, up to Plane639, opposite side up to Plane640, deactivated
  Intersect969: ToIntersect1 Plane643, ToIntersect2 Plane636
  Intersect970: ToIntersect1 Plane636, ToIntersect2 Plane642
  Intersect971: ToIntersect1 Plane646, ToIntersect2 Plane636
  Intersect972: ToIntersect1 Plane647, ToIntersect2 Plane636
  Trim580: Trimmed (Intersect972; Intersect969)
  Trim581: Trimmed (Trim580; Intersect971)
  Trim582: Trimmed (Trim581; Intersect970)
  Pocket199: profile Trim582, up to Plane644, deactivated
  Intersect973: ToIntersect1 Plane645, ToIntersect2 Plane638
  Intersect974: ToIntersect1 Plane646, ToIntersect2 Plane638
  Intersect975: ToIntersect1 Plane638, ToIntersect2 Plane644
  Intersect976: ToIntersect1 Plane647, ToIntersect2 Plane638
  Trim583: Trimmed (Intersect973; Intersect976)
  Trim584: Trimmed (Trim583; Intersect975)
  Trim585: Trimmed (Trim584; Intersect974)
  Pad196: profile LineCorner49, up to Plane639, opposite side up to Plane640, deactivated
  Pocket200: profile Trim585, up to Plane643, deactivated
  Intersect977: ToIntersect1 Plane644, ToIntersect2 Plane637
  Intersect978: ToIntersect1 Plane646, ToIntersect2 Plane637
  Intersect979: ToIntersect1 Plane645, ToIntersect2 Plane637
  Intersect980: ToIntersect1 Plane647, ToIntersect2 Plane637
  Trim586: Trimmed (Intersect977; Intersect980)
  Trim587: Trimmed (Trim586; Intersect979)
  Trim588: Trimmed (Trim587; Intersect978)
  Pad197: profile LineCorner49, up to Plane639, opposite side up to Plane640
  Pocket201: profile Trim588, up to Plane642
Body51 "sugar_cube003Be006"
  Line320: type PtDir, RefPoint vertex of Line5, Direction edge [XY plane of AxisSystem1 | ZX plane of AxisSystem1], Start 0, End 5181.6 {= Body51.X1}
  Line321: type PtDir, RefPoint vertex of Line5, Direction edge [XY plane of AxisSystem1 | ZX plane of AxisSystem1], Start 0, End 5791.2 {= Body51.X2}
  Line322: type PtDir, RefPoint vertex of Line5, Direction edge [YZ plane of AxisSystem1 | XY plane of AxisSystem1], Start 0, End 5791.2 {= Body51.Y1}
  Line323: type PtDir, RefPoint vertex of Line5, Direction edge [YZ plane of AxisSystem1 | XY plane of AxisSystem1], Start 0, End 4572 {= Body51.Y2}
  Line324: type PtDir, RefPoint vertex of Line5, Direction edge [ZX plane of AxisSystem1 | YZ plane of AxisSystem1], Start 0, End 5486.4 {= Body51.Z1}
  Line325: type PtDir, RefPoint vertex of Line5, Direction edge [ZX plane of AxisSystem1 | YZ plane of AxisSystem1], Start 0, End 5486.4 {= Body51.Z2}
  Plane648: type Normal, Curve Line320, RefPoint vertex of Line320
  Plane649: type Normal, Curve Line321, RefPoint vertex of Line321
  Plane650: type Normal, Curve Line322, RefPoint vertex of Line322
  Plane651: type Normal, Curve Line323, RefPoint vertex of Line323
  Plane652: type Normal, Curve Line324, RefPoint vertex of Line324
  Plane653: type Normal, Curve Line325, RefPoint vertex of Line325
  Plane654: type 3Points, Element1 vertex of Line5, Element2 vertex of Line322, Element3 vertex of Line320
  Intersect981: ToIntersect1 Plane650, ToIntersect2 Plane649
  Intersect982: ToIntersect1 Plane648, ToIntersect2 Plane650
  Intersect983: ToIntersect1 Plane648, ToIntersect2 Plane651
  Intersect984: ToIntersect1 Plane651, ToIntersect2 Plane649
  MultiSel50
  LineCorner50: Elements ({intersect ToIntersect1 Plane654, ToIntersect2 Intersect983}; {intersect ToIntersect1 Plane654, ToIntersect2 Intersect984}; {intersect ToIntersect1 Plane654, ToIntersect2 Intersect981}; {intersect ToIntersect1 Plane654, ToIntersect2 Intersect982})
  Pad198: profile LineCorner50, up to Plane652, opposite side up to Plane653, deactivated
  Plane655: type Offset, RefPlane Plane651, Offset 609.6 {= thickness}
  Plane656: type Offset, RefPlane Plane650, Offset 609.6 {= thickness}, reversed
  Plane657: type Offset, RefPlane Plane648, Offset 609.6 {= thickness}, reversed
  Plane658: type Offset, RefPlane Plane649, Offset 609.6 {= thickness}
  Plane659: type Offset, RefPlane Plane653, Offset 609.6 {= thickness}
  Plane660: type Offset, RefPlane Plane652, Offset 609.6 {= thickness}, reversed
  Intersect985: ToIntersect1 Plane655, ToIntersect2 Plane648
  Intersect986: ToIntersect1 Plane656, ToIntersect2 Plane648
  Intersect987: ToIntersect1 Plane659, ToIntersect2 Plane648
  Intersect988: ToIntersect1 Plane660, ToIntersect2 Plane648
  Trim589: Trimmed (Intersect985; Intersect988)
  Trim590: Trimmed (Trim589; Intersect986)
  Trim591: Trimmed (Trim590; Intersect987)
  Pocket202: profile Trim591, up to Plane658, deactivated
  Pad199: profile LineCorner50, up to Plane652, opposite side up to Plane653
  Intersect989: ToIntersect1 Plane656, ToIntersect2 Plane649
  Intersect990: ToIntersect1 Plane649, ToIntersect2 Plane655
  Intersect991: ToIntersect1 Plane659, ToIntersect2 Plane649
  Intersect992: ToIntersect1 Plane660, ToIntersect2 Plane649
  Trim592: Trimmed (Intersect992; Intersect989)
  Trim593: Trimmed (Trim592; Intersect991)
  Trim594: Trimmed (Trim593; Intersect990)
  Pocket203: profile Trim594, up to Plane657
  Intersect993: ToIntersect1 Plane658, ToIntersect2 Plane651
  Intersect994: ToIntersect1 Plane659, ToIntersect2 Plane651
  Intersect995: ToIntersect1 Plane651, ToIntersect2 Plane657
  Intersect996: ToIntersect1 Plane660, ToIntersect2 Plane651
  Trim595: Trimmed (Intersect993; Intersect996)
  Trim596: Trimmed (Trim595; Intersect995)
  Trim597: Trimmed (Trim596; Intersect994)
  Pad200: profile LineCorner50, up to Plane652, opposite side up to Plane653, deactivated
  Pocket204: profile Trim597, up to Plane656, deactivated
  Intersect997: ToIntersect1 Plane657, ToIntersect2 Plane650
  Intersect998: ToIntersect1 Plane659, ToIntersect2 Plane650
  Intersect999: ToIntersect1 Plane658, ToIntersect2 Plane650
  Intersect1000: ToIntersect1 Plane660, ToIntersect2 Plane650
  Trim598: Trimmed (Intersect997; Intersect1000)
  Trim599: Trimmed (Trim598; Intersect999)
  Trim600: Trimmed (Trim599; Intersect998)
  Pad201: profile LineCorner50, up to Plane652, opposite side up to Plane653, deactivated
  Pocket205: profile Trim600, up to Plane655, deactivated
